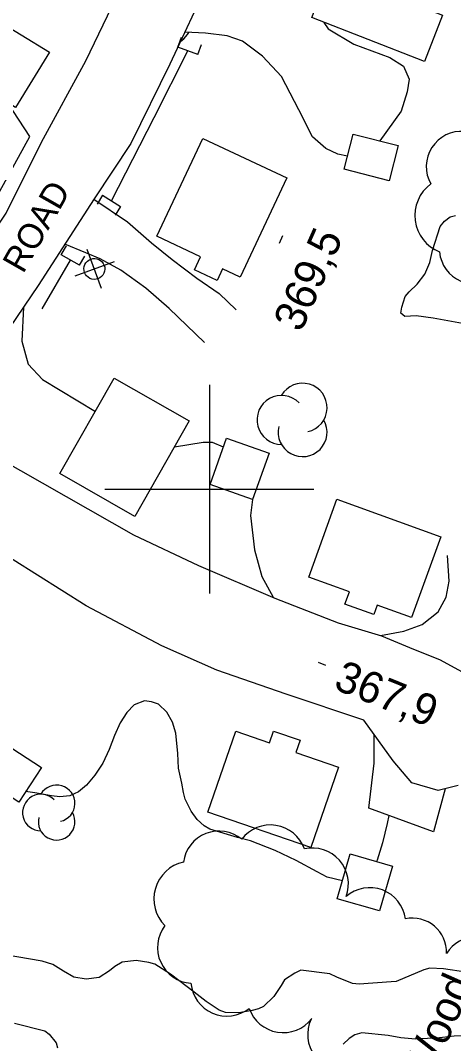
# Model space of a CAD drawing. Extents: x 287698 to 290158, y 5234163 to 5237182.
# Drawn here: x 289181.9 to 289223.4, y 5234946.9 to 5235044.9 of the extents above; entities that cross this region are included whole.
import ezdxf

# ---------------------------------------------------------------- set-up
doc = ezdxf.new("R2010")
doc.units = 0
for name, color, linetype in [('Niveau 1', 7, 'Continuous'), ('Niveau 19', 7, 'Continuous'), ('Niveau 2', 7, 'Continuous'), ('Niveau 21', 7, 'Continuous'), ('Niveau 26', 7, 'Continuous'), ('Niveau 3', 7, 'Continuous'), ('Niveau 31', 7, 'Continuous'), ('Niveau 36', 7, 'Continuous'), ('Niveau 37', 7, 'Continuous'), ('Niveau 4', 7, 'Continuous'), ('Niveau 44', 7, 'Continuous'), ('Niveau 61', 7, 'Continuous')]:
    doc.layers.add(name, color=color, linetype=linetype)

msp = doc.modelspace()

# ---------------------------------------------------------------- linework, layer by layer
at = {"layer": 'Niveau 1'}
msp.add_lwpolyline([(289224.24, 5235015.88), (289221.41, 5235016.38), (289219.78, 5235016.61), (289218.71, 5235016.53), (289218.32, 5235016.85), (289218.42, 5235017.42), (289218.74, 5235018.44), (289219.11, 5235018.9), (289219.89, 5235019.64), (289220.61, 5235020.59), (289221.09, 5235021.7), (289221.35, 5235022.87), (289222.1, 5235025.16), (289222.52, 5235025.67), (289223.06, 5235026.08), (289223.56, 5235026.2)], dxfattribs=at)
at = {"layer": 'Niveau 19'}
for points in [[(289210.96, 5235044.71), (289211.37, 5235044.1), (289213.83, 5235042.61), (289217.28, 5235041.35), (289218.58, 5235040.51), (289219.13, 5235039.28), (289218.92, 5235038.07), (289218.37, 5235036.22), (289216.31, 5235033.36)], [(289213.23, 5235031.88), (289212.29, 5235032.07), (289211.15, 5235032.62), (289209.87, 5235033.76), (289208.56, 5235036.33), (289206.89, 5235039.53), (289205.1, 5235041.47), (289203.16, 5235042.91), (289201.71, 5235043.43), (289199.64, 5235043.69), (289197.65, 5235043.76)], [(289188.93, 5235027.77), (289192.17, 5235025.61), (289194.47, 5235023.6), (289196.44, 5235021.99), (289198.79, 5235020.22), (289200.93, 5235018.75), (289202.56, 5235017.16)], [(289199.53, 5235014.06), (289196.14, 5235017.29), (289193.93, 5235019.25), (289191.51, 5235020.97), (289189.55, 5235022.07), (289188.17, 5235022.64), (289186.17, 5235023.48)], [(289182.21, 5235017.44), (289182.05, 5235014.19), (289182.65, 5235011.96), (289184.02, 5235010.5), (289189.09, 5235007.45)], [(289196.67, 5235004.06), (289199.39, 5235004.5), (289200.26, 5235004.5), (289201.33, 5235004.05)], [(289204.14, 5234999.01), (289203.92, 5234997.48), (289204.32, 5234994.2), (289205.02, 5234991.64), (289206.12, 5234989.64)], [(289216.37, 5234985.98), (289218.6, 5234986.39), (289220.38, 5234987.05), (289221.89, 5234988.26), (289222.68, 5234989.64), (289222.96, 5234991.2), (289222.8, 5234993.63)], [(289215.25, 5234969.45), (289215.78, 5234973.74), (289215.78, 5234976.48)], [(289222.57, 5234971.31), (289221.46, 5234967.18), (289215.25, 5234969.45)]]:
    msp.add_lwpolyline(points, dxfattribs=at)
at = {"layer": 'Niveau 2'}
for points in [[(289197.24, 5235042.88), (289197.56, 5235043.14), (289197.9, 5235043.55), (289198.04, 5235043.75)], [(289210.32, 5234963.35), (289208.32, 5234964.42), (289206.31, 5234965.38), (289203.94, 5234966.32), (289202.68, 5234966.63), (289200.05, 5234967.42), (289199.5, 5234967.76), (289198.82, 5234968.36), (289198.27, 5234969.15), (289197.68, 5234970.31), (289197.51, 5234970.93), (289197.36, 5234971.83), (289197.05, 5234973.29), (289196.97, 5234974.68), (289196.79, 5234976.64), (289196.48, 5234977.67), (289195.94, 5234978.64), (289195.14, 5234979.41), (289194.47, 5234979.63), (289193.79, 5234979.71), (289192.81, 5234979.33), (289192.1, 5234978.61), (289191.46, 5234977.62), (289190.92, 5234976.42), (289190.4, 5234975.07), (289189.8, 5234973.77), (289189.05, 5234972.61), (289188.25, 5234971.65), (289187.46, 5234971), (289186.63, 5234970.62), (289185.67, 5234970.52), (289184.9, 5234970.62), (289183.28, 5234970.9), (289182.41, 5234971.05)], [(289217.19, 5234968.74), (289217.03, 5234967.98), (289216.58, 5234966.11), (289216.06, 5234964.45), (289216.01, 5234964.34)], [(289212.73, 5234962.47), (289211.27, 5234962.82), (289210.32, 5234963.35)], [(289211.53, 5234953.57), (289208.74, 5234953.93), (289208.18, 5234953.63), (289207.18, 5234953.01), (289206.86, 5234952.46), (289206.17, 5234951.42), (289205.17, 5234950.46), (289204.7, 5234950.24), (289204.1, 5234950.08), (289202.82, 5234949.84), (289201.55, 5234949.86), (289200.94, 5234950.09), (289199.68, 5234950.92), (289198.54, 5234951.81), (289196.27, 5234953.55), (289194.77, 5234954.51), (289194.21, 5234954.65), (289193, 5234954.84), (289191.66, 5234954.69), (289190.95, 5234954.29), (289190.43, 5234953.85), (289189.46, 5234953.21), (289188.2, 5234953.05), (289187.04, 5234953.27), (289186.04, 5234953.83), (289185, 5234954.48), (289183.98, 5234954.79), (289182.69, 5234955.01), (289179.48, 5234955.56)], [(289242.05, 5234952.66), (289241.25, 5234952.65), (289240.23, 5234952.82), (289237.13, 5234953.34), (289236.16, 5234953.42), (289233.17, 5234953.98), (289231.05, 5234954.29), (289230.7, 5234954.2), (289227.72, 5234953.72), (289226.36, 5234953.63), (289224.56, 5234953.73), (289222.4, 5234954.06), (289221.09, 5234954.13), (289220.52, 5234953.97), (289217.88, 5234952.85), (289217.39, 5234952.81), (289214.35, 5234952.58), (289213.71, 5234952.64), (289212.19, 5234953.25), (289211.53, 5234953.57)], [(289181.34, 5234948.85), (289184.24, 5234948.12), (289184.65, 5234947.8), (289185.34, 5234946.97), (289185.46, 5234946.48)], [(289226.9, 5234947.66), (289223.42, 5234947.61), (289222.04, 5234947.45), (289219.72, 5234947.33), (289218.32, 5234947.45), (289217.12, 5234947.66), (289214.59, 5234947.93), (289213.92, 5234947.72), (289213.39, 5234947.37), (289212.81, 5234946.84)]]:
    msp.add_lwpolyline(points, dxfattribs=at)
at = {"layer": 'Niveau 21'}
for points in [[(289199.94, 5235048.71), (289196.23, 5235040.7), (289192.47, 5235033.11), (289188.96, 5235027.82), (289183.62, 5235019.52), (289177.43, 5235010.42), (289175.97, 5235008.02), (289175.74, 5235006.72), (289176.1, 5235005.31), (289177.52, 5235004.29), (289192.73, 5234995.64), (289198.97, 5234992.69), (289206.28, 5234989.57), (289212.33, 5234987.21), (289216.47, 5234985.95), (289219.53, 5234984.66), (289222.04, 5234983.69), (289224.54, 5234982.31)], [(289123.87, 5235045.95), (289133.91, 5235042.58), (289140.1, 5235039.99), (289144.42, 5235037.76), (289154.52, 5235032.65), (289161.69, 5235028.28), (289168.09, 5235024.81), (289172.36, 5235022.64), (289174.08, 5235022.15), (289175.89, 5235022.18), (289178.03, 5235023), (289179.28, 5235024.59), (289180.56, 5235026.45), (289183.92, 5235033.25), (289188.17, 5235041.03), (289191.48, 5235047.94)], [(289223.81, 5234971.62), (289221.9, 5234971.14), (289219.39, 5234971.87), (289217.59, 5234973.99), (289214.78, 5234977.86), (289207.36, 5234980.37), (289200.72, 5234982.65), (289195.46, 5234984.98), (289188.22, 5234988.84), (289178.86, 5234994.69), (289171.79, 5234999.07), (289169.95, 5234999.21), (289169.25, 5234998.5), (289166.8, 5234995.42), (289160.01, 5234984.92), (289153.93, 5234975.77), (289148.33, 5234967.48), (289147.29, 5234965.05), (289146.91, 5234962.9), (289146.82, 5234960.76), (289147.54, 5234958.89), (289152.24, 5234951.54), (289157.04, 5234944.68)]]:
    msp.add_lwpolyline(points, dxfattribs=at)
at = {"layer": 'Niveau 26'}
for p, q in [((289196.99, 5235042.35), (289197.34, 5235043.28)), ((289198.89, 5235041.64), (289196.99, 5235042.35)), ((289198.89, 5235041.64), (289199.24, 5235042.58)), ((289189.78, 5235028.15), (289189.25, 5235027.3)), ((289189.78, 5235028.15), (289191.5, 5235027.08)), ((289191.5, 5235027.08), (289190.97, 5235026.23)), ((289185.82, 5235022.45), (289186.31, 5235023.32)), ((289187.57, 5235021.44), (289185.82, 5235022.45)), ((289187.57, 5235021.44), (289188.07, 5235022.31))]:
    msp.add_line(p, q, dxfattribs=at)
at = {"layer": 'Niveau 3'}
for p, q in [((289206.72, 5235023.55), (289207.04, 5235024.28)), ((289210.4, 5234983.43), (289211.13, 5234983.13))]:
    msp.add_line(p, q, dxfattribs=at)
at = {"layer": 'Niveau 31'}
for points in [[(289209.82, 5235045.16), (289213.71, 5235055.14), (289221.45, 5235052.11), (289219.28, 5235046.58), (289222.32, 5235045.4), (289220.58, 5235040.95)], [(289170.94, 5235037.69), (289176.53, 5235046.83), (289184.68, 5235041.85), (289181.44, 5235036.55), (289180.25, 5235037.28), (289178, 5235033.61), (289176.21, 5235034.7), (289175.63, 5235033.73), (289173.08, 5235035.29), (289173.56, 5235036.08)], [(289213.77, 5235034.01), (289218.08, 5235032.91), (289217.22, 5235029.54), (289212.91, 5235030.64)], [(289194.98, 5235024.22), (289199.37, 5235033.59), (289207.41, 5235029.82), (289202.95, 5235020.31), (289201.27, 5235021.09), (289200.76, 5235019.98), (289198.58, 5235021.01), (289199.16, 5235022.25)], [(289198.08, 5235006.53), (289192.86, 5234997.39), (289185.69, 5235001.49), (289190.9, 5235010.62)], [(289204.14, 5234999.01), (289200.06, 5235000.46), (289201.63, 5235004.89), (289205.71, 5235003.44)], [(289212.21, 5234999.03), (289222.16, 5234995.44), (289219.36, 5234987.7), (289216.05, 5234988.9), (289215.73, 5234987.99), (289212.98, 5234988.98), (289213.41, 5234990.18), (289209.52, 5234991.58)], [(289209.7, 5234965.67), (289199.86, 5234969.05), (289202.53, 5234976.82), (289205.77, 5234975.7), (289206.15, 5234976.82), (289208.68, 5234975.95), (289208.27, 5234974.77), (289212.35, 5234973.36)], [(289178.29, 5234972.29), (289180.46, 5234975.61), (289183.92, 5234973.35), (289181.75, 5234970.03)], [(289213.49, 5234965.07), (289217.54, 5234963.9), (289216.29, 5234959.6), (289212.24, 5234960.77)]]:
    msp.add_lwpolyline(points, close=True, dxfattribs=at)
at = {"layer": 'Niveau 36'}
for p, q in [((289189.68, 5235019.21), (289188.31, 5235022.96)), ((289190.87, 5235021.77), (289187.12, 5235020.4))]:
    msp.add_line(p, q, dxfattribs=at)
msp.add_ellipse((289188.992, 5235021.093), major_axis=(-0.907, 0.42), ratio=0.999982, dxfattribs=at)
at = {"layer": 'Niveau 37'}
msp.add_lwpolyline([(289165.89, 5235030.13), (289166.61, 5235027.87), (289173.3, 5235024.76), (289176.81, 5235025.83), (289179.37, 5235027.55), (289182.8, 5235033.77), (289180.7, 5235037)], dxfattribs=at)
at = {"layer": 'Niveau 4'}
for points in [[(289190.63, 5235027.62), (289194.73, 5235035.59), (289197.95, 5235041.99)], [(289183.99, 5235017.26), (289186.7, 5235021.94)]]:
    msp.add_lwpolyline(points, dxfattribs=at)
at = {"layer": 'Niveau 44'}
for centre, radius, start, end in [((289223.429, 5235026.21), 3.76, 126.54927, 248.15549), ((289208.922, 5235007.805), 2.345, 282.26917, 149.72626), ((289206.905, 5235006.632), 2.345, 44.11537, 269.80396), ((289208.922, 5235005.46), 2.345, 166.93686, 29.62123), ((289185.379, 5234969.904), 1.755, 282.26917, 149.72626), ((289183.87, 5234969.027), 1.755, 44.11537, 269.80396), ((289185.379, 5234968.149), 1.755, 166.93686, 29.62123), ((289200.913, 5234963.812), 3.435, 50.44316, 172.16662)]:
    msp.add_arc(centre, radius, start, end, dxfattribs=at)
for centre, major_axis, ratio, start_param, end_param in [((289224.156, 5235030.882), (-1.833, -2.858), 0.999984, 3.634174, 5.790604), ((289225.41, 5235023.032), (3.127, -1.321), 0.99986, 3.633576, 5.7693), ((289205.849, 5234964.398), (-3.397, 0.522), 0.999453, 3.632944, 5.791834), ((289209.857, 5234962.178), (-2.274, 2.593), 0.999448, 3.637697, 5.787081), ((289198.315, 5234960.744), (-3.487, 1), 0.999682, 5.215579, 7.343903), ((289215.354, 5234958.396), (-3.214, 1.213), 0.999454, 3.632191, 5.792587), ((289219.315, 5234955.528), (2.418, 2.444), 0.965384, 5.47536, 7.245603), ((289198.471, 5234956.101), (1.419, -3.133), 0.999619, 3.63424, 5.790538), ((289225.824, 5234953.457), (-0.843, 3.663), 0.999982, 5.218407, 7.04117), ((289201.669, 5234952.965), (3.161, -1.362), 0.999452, 3.634428, 5.79035), ((289207.065, 5234951.385), (3.396, -0.556), 0.99962, 3.634064, 5.790714), ((289212.846, 5234947.762), (2.059, -2.756), 0.99962, 3.633498, 5.79128)]:
    msp.add_ellipse(centre, major_axis=major_axis, ratio=ratio, start_param=start_param, end_param=end_param, dxfattribs=at)
at = {"layer": 'Niveau 61'}
for points in [[(289200, 5235010), (289200, 5235000), (289200, 5234990)], [(289190, 5235000), (289200, 5235000), (289210, 5235000)]]:
    msp.add_lwpolyline(points, dxfattribs=at)

# ---------------------------------------------------------------- texts
at = {"layer": 'Niveau 21'}
msp.add_text('ROAD', height=2.4, rotation=60.29148, dxfattribs=at).set_placement((289182.17, 5235020.56))
at = {"layer": 'Niveau 3'}
for s, rotation, p in [('369,5', 66.1217, (289208.77, 5235014.93)), ('367,9', 337.93372, (289211.77, 5234980.92))]:
    msp.add_text(s, height=3, rotation=rotation, dxfattribs=at).set_placement(p)
at = {"layer": 'Niveau 44'}
msp.add_text('Wood', height=3, rotation=66.1217, dxfattribs=at).set_placement((289221.07, 5234943.11))

doc.saveas('drawing.dxf')
